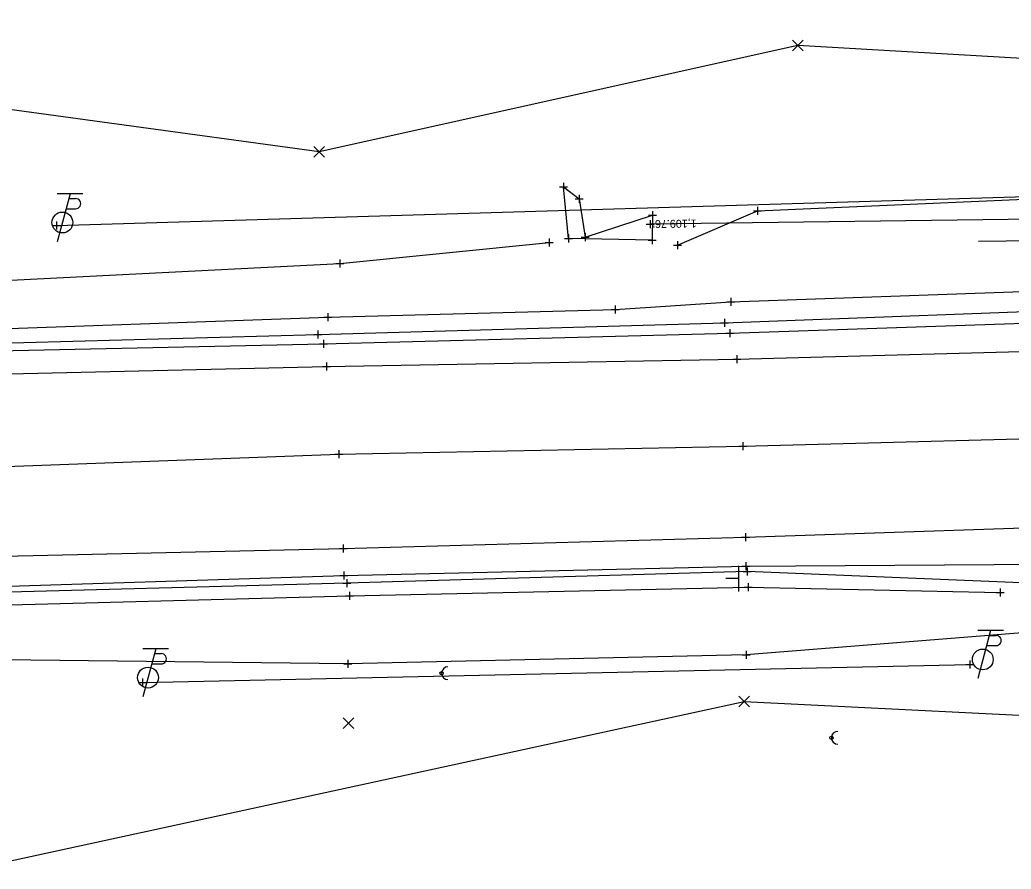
# Model space of a CAD drawing. Extents: x 2402028 to 2407435, y 498611 to 499105.
# Drawn here: x 2402849.5 to 2402973.4, y 498611.7 to 498717.9 of the extents above; entities that cross this region are included whole.
import ezdxf

# ---------------------------------------------------------------- set-up
doc = ezdxf.new("R2010")
doc.units = 0
for name, color, linetype in [('DR_X_Ditch', 7, 'Continuous'), ('DR_X_Storm_Sewer', 7, 'Continuous'), ('DR_X_Text', 7, 'Continuous'), ('PV_X_COP', 7, 'Continuous'), ('PV_X_EOP', 7, 'Continuous'), ('PV_X_Shoulder', 7, 'Continuous'), ('RD_X_GR_Lt', 7, 'Continuous'), ('RW_X_CL_1000_Stations', 7, 'Continuous'), ('RW_X_CL_500_Bearings', 7, 'Continuous'), ('RW_X_CL_500_Cardinal_Points', 7, 'Continuous'), ('RW_X_CL_500_Distances', 7, 'Continuous'), ('RW_X_CL_500_Stations', 7, 'Continuous'), ('SC_Scratch1', 7, 'Continuous'), ('SV_X_Break_Lines', 7, 'Continuous'), ('SV_X_Terrain_Boundary', 7, 'Continuous'), ('UT_X_Telecom', 7, 'Continuous')]:
    doc.layers.add(name, color=color, linetype=linetype)

msp = doc.modelspace()

# ---------------------------------------------------------------- linework, layer by layer
at = {"layer": 'DR_X_Ditch'}
msp.add_lwpolyline([(2402928.55, 498693.45), (2402928.5, 498690.31), (2402918.06, 498690.53), (2402917.44, 498696.96), (2402919.38, 498695.5), (2402920.12, 498690.7)], close=True, dxfattribs=at)
at = {"layer": 'DR_X_Storm_Sewer'}
msp.add_line((2403033.33, 498693.66), (2402928.26, 498692.31), dxfattribs=at)
at = {"layer": 'DR_X_Text'}
msp.add_line((2402969.29, 498690.19), (2402988.37, 498690.43), dxfattribs=at)
at = {"layer": 'PV_X_COP'}
msp.add_lwpolyline([(2402290.78, 498650.6), (2402340.95, 498651.54), (2402390.57, 498652.34), (2402439.7, 498652.49), (2402489.93, 498654.64), (2402539.81, 498655.53), (2402589.95, 498657.15), (2402640.38, 498659.77), (2402689.17, 498658.83), (2402739.11, 498659.65), (2402789.43, 498660.95), (2402839.82, 498661.75), (2402889.36, 498663.57), (2402939.81, 498664.58), (2402990.03, 498665.92), (2403038.83, 498667.68), (2403088.96, 498668.97), (2403139.3, 498669.99), (2403188.98, 498670.93), (2403236.78, 498672.43), (2403288.95, 498673.92), (2403339.4, 498675.07), (2403388.6, 498676.54)], dxfattribs=at)
at = {"layer": 'PV_X_EOP'}
for points in [[(2402289.63, 498661.52), (2402339.86, 498662.34), (2402390.35, 498663.57), (2402439.38, 498664.47), (2402489.03, 498665.67), (2402538.63, 498666.7), (2402622.2, 498668.45), (2402639.44, 498668.97), (2402688.21, 498669.91), (2402738.3, 498670.77), (2402784.26, 498671.54), (2402839.07, 498673.4), (2402887.81, 498674.54), (2402939.07, 498675.44), (2402989.96, 498676.81), (2403039.49, 498677.82), (2403088.59, 498679.54), (2403138.58, 498681), (2403188.48, 498682.36), (2403236.31, 498683.8), (2403287.8, 498685.14), (2403338.61, 498686.54), (2403387.34, 498688.53)], [(2402290.91, 498639.29), (2402341.07, 498640.3), (2402390.61, 498641.23), (2402440.65, 498642.38), (2402490.15, 498643.23), (2402540.35, 498644.45), (2402590.8, 498645.77), (2402640.33, 498646.73), (2402690.18, 498647.64), (2402739.92, 498648.63), (2402790, 498649.56), (2402840.05, 498650.65), (2402889.89, 498651.78), (2402940.17, 498653.2), (2402989.78, 498654.87), (2403039.63, 498656.02), (2403089.54, 498657.39), (2403140.04, 498658.56), (2403189.82, 498659.81), (2403238.57, 498661.04), (2403289.76, 498662.62), (2403340.13, 498663.91), (2403389.07, 498665.43)]]:
    msp.add_lwpolyline(points, dxfattribs=at)
at = {"layer": 'PV_X_Shoulder'}
for p, q in [((2402938.19, 498678.69), (2402988.67, 498680.4)), ((2402887.44, 498677.34), (2402938.19, 498678.69)), ((2402838.76, 498676.31), (2402887.44, 498677.34))]:
    msp.add_line(p, q, dxfattribs=at)
msp.add_lwpolyline([(2402291.13, 498635.58), (2402341.06, 498636.96), (2402390.62, 498637.69), (2402440.73, 498638.55), (2402490.3, 498639.85), (2402540.78, 498641.01), (2402590.73, 498641.96), (2402640.23, 498642.72), (2402690.38, 498643.95), (2402740.06, 498644.93), (2402790, 498645.7), (2402840.23, 498646.8), (2402889.99, 498648.42), (2402940.22, 498649.59), (2402989.85, 498649.92), (2403040.06, 498650.63), (2403089.93, 498652.73), (2403140.24, 498654.26), (2403189.57, 498655.62), (2403238.67, 498657.76), (2403289.89, 498659.04), (2403340.12, 498659.5), (2403389.1, 498660.69)], dxfattribs=at)
at = {"layer": 'RD_X_GR_Lt'}
for points in [[(2402671.34, 498674.03), (2402687.6, 498674.22), (2402737.25, 498674.66), (2402787.14, 498675.21), (2402837.72, 498677.2), (2402886.73, 498678.51), (2402937.55, 498679.97), (2402988.38, 498681.88), (2403034.42, 498684.03)], [(2402983.63, 498647.12), (2402940.38, 498648.9), (2402890.36, 498647.43), (2402840.29, 498646.11), (2402790.18, 498644.6), (2402758.45, 498643.74)]]:
    msp.add_lwpolyline(points, dxfattribs=at)
at = {"layer": 'RW_X_CL_1000_Stations'}
for p, q in [((2402939.3, 498649.62), (2402939.3, 498646.42)), ((2402939.3, 498648.02), (2402937.7, 498648.02))]:
    msp.add_line(p, q, dxfattribs=at)
at = {"layer": 'RW_X_CL_500_Bearings'}
for p, q in [((2402916.94, 498696.96), (2402917.94, 498696.96)), ((2402917.44, 498697.46), (2402917.44, 498696.46)), ((2402917.44, 498696.96), (2402917.44, 498696.96)), ((2402919.38, 498696), (2402919.38, 498695)), ((2402918.88, 498695.5), (2402919.88, 498695.5)), ((2402919.38, 498695.5), (2402919.38, 498695.5)), ((2402941.65, 498694.47), (2402941.65, 498693.47)), ((2402928.05, 498693.45), (2402929.05, 498693.45)), ((2402928.55, 498693.95), (2402928.55, 498692.95)), ((2402928.55, 498693.45), (2402928.55, 498693.45)), ((2402941.15, 498693.97), (2402942.15, 498693.97)), ((2402941.65, 498693.97), (2402941.65, 498693.97)), ((2402853.58, 498692.14), (2402854.58, 498692.14)), ((2402854.08, 498692.64), (2402854.08, 498691.64)), ((2402854.08, 498692.14), (2402854.08, 498692.14)), ((2402918.06, 498691.03), (2402918.06, 498690.03)), ((2402919.62, 498690.7), (2402920.62, 498690.7)), ((2402920.12, 498691.2), (2402920.12, 498690.2)), ((2402920.12, 498690.7), (2402920.12, 498690.7)), ((2402928.5, 498690.81), (2402928.5, 498689.81)), ((2402915.11, 498690.01), (2402916.11, 498690.01)), ((2402915.61, 498690.51), (2402915.61, 498689.51)), ((2402915.61, 498690.01), (2402915.61, 498690.01)), ((2402917.56, 498690.53), (2402918.56, 498690.53)), ((2402918.06, 498690.53), (2402918.06, 498690.53)), ((2402928, 498690.31), (2402929, 498690.31)), ((2402928.5, 498690.31), (2402928.5, 498690.31)), ((2402931.15, 498689.7), (2402932.15, 498689.7)), ((2402931.65, 498690.2), (2402931.65, 498689.2)), ((2402931.65, 498689.7), (2402931.65, 498689.7)), ((2402888.98, 498687.41), (2402889.98, 498687.41)), ((2402889.48, 498687.91), (2402889.48, 498686.91)), ((2402889.48, 498687.41), (2402889.48, 498687.41)), ((2402923.89, 498682.13), (2402923.89, 498681.13)), ((2402937.81, 498682.59), (2402938.81, 498682.59)), ((2402938.31, 498683.09), (2402938.31, 498682.09)), ((2402938.31, 498682.59), (2402938.31, 498682.59)), ((2402887.97, 498681.18), (2402887.97, 498680.18)), ((2402923.39, 498681.63), (2402924.39, 498681.63)), ((2402923.89, 498681.63), (2402923.89, 498681.63)), ((2402887.47, 498680.68), (2402888.47, 498680.68)), ((2402887.97, 498680.68), (2402887.97, 498680.68)), ((2402937.05, 498679.97), (2402938.05, 498679.97)), ((2402937.55, 498680.47), (2402937.55, 498679.47)), ((2402937.55, 498679.97), (2402937.55, 498679.97)), ((2402886.23, 498678.51), (2402887.23, 498678.51)), ((2402886.73, 498679.01), (2402886.73, 498678.01)), ((2402886.73, 498678.51), (2402886.73, 498678.51)), ((2402937.69, 498678.69), (2402938.69, 498678.69)), ((2402938.19, 498679.19), (2402938.19, 498678.19)), ((2402938.19, 498678.69), (2402938.19, 498678.69)), ((2402886.94, 498677.34), (2402887.94, 498677.34)), ((2402887.44, 498677.84), (2402887.44, 498676.84)), ((2402887.44, 498677.34), (2402887.44, 498677.34)), ((2402939.07, 498675.94), (2402939.07, 498674.94)), ((2402887.81, 498675.04), (2402887.81, 498674.04)), ((2402938.57, 498675.44), (2402939.57, 498675.44)), ((2402939.07, 498675.44), (2402939.07, 498675.44)), ((2402887.31, 498674.54), (2402888.31, 498674.54)), ((2402887.81, 498674.54), (2402887.81, 498674.54)), ((2402939.81, 498665.08), (2402939.81, 498664.08)), ((2402888.86, 498663.57), (2402889.86, 498663.57)), ((2402889.36, 498664.07), (2402889.36, 498663.07)), ((2402889.36, 498663.57), (2402889.36, 498663.57)), ((2402939.31, 498664.58), (2402940.31, 498664.58)), ((2402939.81, 498664.58), (2402939.81, 498664.58)), ((2402940.17, 498653.7), (2402940.17, 498652.7)), ((2402939.67, 498653.2), (2402940.67, 498653.2)), ((2402940.17, 498653.2), (2402940.17, 498653.2)), ((2402889.39, 498651.78), (2402890.39, 498651.78)), ((2402889.89, 498652.28), (2402889.89, 498651.28)), ((2402889.89, 498651.78), (2402889.89, 498651.78)), ((2402940.22, 498650.09), (2402940.22, 498649.09)), ((2402889.99, 498648.92), (2402889.99, 498647.92)), ((2402939.72, 498649.59), (2402940.72, 498649.59)), ((2402939.88, 498648.9), (2402940.88, 498648.9)), ((2402940.22, 498649.59), (2402940.22, 498649.59)), ((2402940.38, 498649.4), (2402940.38, 498648.4)), ((2402940.38, 498648.9), (2402940.38, 498648.9)), ((2402889.49, 498648.42), (2402890.49, 498648.42)), ((2402889.86, 498647.43), (2402890.86, 498647.43)), ((2402889.99, 498648.42), (2402889.99, 498648.42)), ((2402890.36, 498647.93), (2402890.36, 498646.93)), ((2402890.36, 498647.43), (2402890.36, 498647.43)), ((2402940.48, 498647.46), (2402940.48, 498646.46)), ((2402890.67, 498646.35), (2402890.67, 498645.35)), ((2402939.98, 498646.96), (2402940.98, 498646.96)), ((2402940.48, 498646.96), (2402940.48, 498646.96)), ((2402971.49, 498646.28), (2402972.49, 498646.28)), ((2402971.99, 498646.78), (2402971.99, 498645.78)), ((2402971.99, 498646.28), (2402971.99, 498646.28)), ((2402890.17, 498645.85), (2402891.17, 498645.85)), ((2402890.67, 498645.85), (2402890.67, 498645.85)), ((2402940.23, 498639), (2402940.23, 498638)), ((2402890.46, 498637.88), (2402890.46, 498636.88)), ((2402939.73, 498638.5), (2402940.73, 498638.5)), ((2402940.23, 498638.5), (2402940.23, 498638.5)), ((2402968.18, 498637.76), (2402968.18, 498636.76)), ((2402889.96, 498637.38), (2402890.96, 498637.38)), ((2402890.46, 498637.38), (2402890.46, 498637.38)), ((2402967.68, 498637.26), (2402968.68, 498637.26)), ((2402968.18, 498637.26), (2402968.18, 498637.26)), ((2402864.3, 498635.01), (2402865.3, 498635.01)), ((2402864.8, 498635.51), (2402864.8, 498634.51)), ((2402864.8, 498635.01), (2402864.8, 498635.01))]:
    msp.add_line(p, q, dxfattribs=at)
at = {"layer": 'RW_X_CL_500_Cardinal_Points'}
for p, q in [((2402855.77, 498696.12), (2402854.16, 498690.12)), ((2402857.37, 498696.12), (2402854.17, 498696.12)), ((2402855.61, 498695.52), (2402856.46, 498695.52)), ((2402855.27, 498694.25), (2402856.46, 498694.25)), ((2402970.78, 498641.51), (2402969.17, 498635.51)), ((2402972.38, 498641.51), (2402969.18, 498641.51)), ((2402970.62, 498640.91), (2402971.47, 498640.91)), ((2402868.07, 498639.24), (2402864.87, 498639.24)), ((2402866.47, 498639.24), (2402864.87, 498633.24)), ((2402970.27, 498639.64), (2402971.47, 498639.64)), ((2402866.31, 498638.64), (2402867.16, 498638.64)), ((2402865.97, 498637.36), (2402867.16, 498637.36))]:
    msp.add_line(p, q, dxfattribs=at)
for centre, radius in [((2402854.81, 498692.52), 1.3), ((2402969.81, 498637.91), 1.3), ((2402865.51, 498635.64), 1.3), ((2402902.19, 498636.19), 0.2), ((2402950.9, 498628.12), 0.2)]:
    msp.add_circle(centre, radius, dxfattribs=at)
for centre, radius, start, end in [((2402856.47, 498694.88), 0.638, 268.8767, 91.1233), ((2402971.48, 498640.28), 0.638, 268.8767, 91.1233), ((2402867.18, 498638), 0.638, 268.8767, 91.1233), ((2402902.99, 498636.19), 0.8, 90, 270), ((2402951.7, 498628.12), 0.8, 90, 270)]:
    msp.add_arc(centre, radius, start, end, dxfattribs=at)
at = {"layer": 'RW_X_CL_500_Distances'}
for p, q in [((2402927.76, 498692.31), (2402928.76, 498692.31)), ((2402928.26, 498692.81), (2402928.26, 498691.81)), ((2402928.26, 498692.31), (2402928.26, 498692.31))]:
    msp.add_line(p, q, dxfattribs=at)
at = {"layer": 'RW_X_CL_500_Stations'}
for p, q in [((2402946.05, 498713.96), (2402947.38, 498715.3)), ((2402946.05, 498715.3), (2402947.38, 498713.96)), ((2402886.24, 498700.69), (2402887.57, 498702.02)), ((2402886.24, 498702.02), (2402887.57, 498700.69)), ((2402939.31, 498631.99), (2402940.65, 498633.32)), ((2402939.31, 498633.32), (2402940.65, 498631.99)), ((2402889.89, 498629.29), (2402891.22, 498630.63)), ((2402889.89, 498630.63), (2402891.22, 498629.29))]:
    msp.add_line(p, q, dxfattribs=at)
at = {"layer": 'SV_X_Break_Lines'}
for points in [[(2402288.25, 498667.48), (2402339.69, 498668.17), (2402389.86, 498669.48), (2402438.42, 498670.54), (2402588.11, 498673.81), (2402638.99, 498674.42), (2402672.44, 498676.2), (2402688.28, 498675.46), (2402738.27, 498675.88), (2402788.35, 498678.35), (2402793.91, 498678.03), (2402796.15, 498678.69), (2402799.15, 498678), (2402838.74, 498678.94), (2402887.97, 498680.68), (2402923.89, 498681.63), (2402938.31, 498682.59), (2402988.84, 498684.41), (2403028.61, 498685.67), (2403039.38, 498686.37), (2403044.21, 498687.92), (2403044.42, 498694.26), (2403040.83, 498698.9), (2403035.04, 498699.28)], [(2402931.65, 498689.7), (2402941.65, 498693.97), (2402986.48, 498695.95), (2403027.13, 498694.57), (2403031.07, 498695.35)], [(2402803.94, 498686.28), (2402839.28, 498684.84), (2402889.48, 498687.41), (2402915.61, 498690.01)], [(2402760.32, 498641.79), (2402790.31, 498643.78), (2402840.36, 498644.53), (2402890.67, 498645.85), (2402940.48, 498646.96), (2402971.99, 498646.28)], [(2402976.32, 498641.36), (2402940.23, 498638.5), (2402890.46, 498637.38), (2402840.04, 498637.93), (2402803.61, 498636.34), (2402801.54, 498636.51), (2402797.21, 498636.06), (2402793.66, 498636.1), (2402790.59, 498637.18), (2402761.78, 498637.43)]]:
    msp.add_lwpolyline(points, dxfattribs=at)
at = {"layer": 'SV_X_Terrain_Boundary'}
for points in [[(2403390.54, 498717.85), (2403340.67, 498716.01), (2403291.04, 498712.96), (2403238.44, 498711.46), (2403188.93, 498712.35), (2403141.78, 498709.87), (2403108.52, 498702.31), (2403030.94, 498708.33), (2402991.96, 498712.04), (2402946.72, 498714.63), (2402886.9, 498701.35), (2402808.26, 498712.11), (2402805.63, 498711.55), (2402802.55, 498713.98), (2402800.83, 498712.58), (2402791.73, 498715.48), (2402739.88, 498694.44), (2402686.71, 498702.37), (2402636.92, 498697.87)], [(2402641.3, 498620.88), (2402692.24, 498622.71), (2402740.26, 498624.67), (2402793.66, 498636.1), (2402843.48, 498611.7), (2402939.98, 498632.65), (2402988.61, 498630.24), (2403041.47, 498629.99), (2403091.65, 498630.18), (2403191.21, 498636.27), (2403240.26, 498637.09), (2403290.41, 498638.6), (2403346.11, 498636.26), (2403438.36, 498646.02)]]:
    msp.add_lwpolyline(points, dxfattribs=at)
at = {"layer": 'UT_X_Telecom'}
for points in [[(2402854.08, 498692.14), (2403014.26, 498696.95)], [(2402864.8, 498635.01), (2402968.18, 498637.26)]]:
    msp.add_lwpolyline(points, dxfattribs=at)

# ---------------------------------------------------------------- texts
at = {"layer": 'SC_Scratch1'}
msp.add_text("1,109.76'", height=1, rotation=180.7345, dxfattribs=at).set_placement((2402934.05, 498692.89))

doc.saveas('drawing.dxf')
